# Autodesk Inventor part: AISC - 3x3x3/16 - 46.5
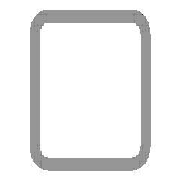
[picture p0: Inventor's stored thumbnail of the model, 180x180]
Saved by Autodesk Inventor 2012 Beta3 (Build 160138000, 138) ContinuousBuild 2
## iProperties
IsCustomPart: 1
Created: 2011-01
Part Number: AISC - 3x3x3/16 - 46.5
Material: Steel, Mild
Description: Tube
Document SubType Name: Modeling
Standard: ANSI
Designer: Beta-8540w
Standards Organization: ANSI
Language: en-US
Size Designation: 3x3x3/16
Categories: <MemberInstance><Categories><Category DisplayName="Structural Shapes" InternalName="089c4875-fa83-4c05-b084-43b9cc11f5ed" Mnemonic="GRDR"><CategoryParameter Dis
Stock Number: 3x3x3/16
Density: 7.86 g/cm^3
_CCFamilyMember: 9
_CCFamilyDisplayName: ANSI AISC (Square) - Tube
_FrameMemberDoc: Frame Member File
_Version: 15.0.0
_GetPNFromCC: 1
G_L: 46.500 in
G_W: 3.000 in
G_H: 3.000 in
Author: Beta-8540w
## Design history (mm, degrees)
node "Start plane"
node "End plane"
sketch "Sketch"
  geometry: L1 (-38.1, -28.575)-(-38.1, 28.575); L2 (-28.575, 38.1)-(28.575, 38.1); L3 (38.1, 28.575)-(38.1, -28.575); L4 (28.575, -38.1)-(-28.575, -38.1); L5 (-28.575, 33.337)-(28.575, 33.338); L6 (33.338, 28.575)-(33.338, -28.575); L7 (28.575, -33.337)-(-28.575, -33.338); L8 (-33.338, -28.575)-(-33.338, 28.575); L9 (0, 56.102)-(0, -56.102) reference; L10 (-56.102, 0)-(56.102, 0) reference; A1 r 9.525 centre (-28.575, -28.575) between (-38.1, -28.575) and (-28.575, -38.1); A2 r 9.525 centre (-28.575, 28.575) between (-28.575, 38.1) and (-38.1, 28.575); A3 r 9.525 centre (28.575, 28.575) between (38.1, 28.575) and (28.575, 38.1); A4 r 9.525 centre (28.575, -28.575) between (28.575, -38.1) and (38.1, -28.575); A5 r 4.763 centre (-28.575, 28.575) between (-28.575, 33.337) and (-33.338, 28.575); A6 r 4.763 centre (28.575, 28.575) between (33.338, 28.575) and (28.575, 33.338); A7 r 4.763 centre (28.575, -28.575) between (28.575, -33.337) and (33.338, -28.575); A8 r 4.763 centre (-28.575, -28.575) between (-33.338, -28.575) and (-28.575, -33.338)
  constraints: 16 end point, 16 point on circle, 8 centre point, 8 tangent, 4 parallel, 3 equal radius, 2 perpendicular, 7 other
  dimensions: "d10" = 76.2 distance between parallel lines of L2 L4 (= G_H); "d11" = 76.2 distance between parallel lines of L1 L3 (= G_W); "d12" = 4.7625 distance between parallel lines of L3 L6 (= G_T); "d15" = 38.1 distance between parallel lines of L2 L10 (= 0.5 x d10); "d16" = 38.1 distance between parallel lines of L9 L3 (= 0.5 x d11); "d17" = 9.525 radius of A1 (= G_IR)
extrude "Body" new body sketch "Sketch" stored distance "d3" = 1181.1 (= G_L); taper "d4" = 0 deg
node "Driven Length"
  sketch "Sketch3"
    geometry: L1 (0, 0)-(10, 0) reference
    constraints: 2 end point, 1 horizontal
  workplane "Work Plane3"
  sketch "Sketch4"
    geometry: L1 (-2, 0)-(12, 0) reference; L2 (-2, 1181.1)-(12, 1181.1) reference
    dimensions: "d19" = 1181.1 distance between parallel lines of L1 L2 (derived)
workplane "Work Plane4"
split "Split1"
body "Solid1"
other parameters: "G_W" = 76.2 [user parameter; used in 1 equation term], "G_H" = 76.2 [user parameter; used in 1 equation term], "G_T" = 4.7625 [user parameter; used in 1 equation term], "G_IR" = 9.525 [user parameter; used in 1 equation term], "G_L" = 1181.1 (= d19) [user parameter; used in 1 equation term], "G_OFFSET_START" = 0 [user parameter; used in 1 equation term], "G_OFFSET_END" = -38.1 [user parameter; used in 1 equation term], "d13" = 0 (computed from G_OFFSET_START), "d14" = 1181.1 (= G_OFFSET_END + B_L), "B_L" = 1219.2 [user parameter; used in 1 equation term], "d18" = 90 deg
